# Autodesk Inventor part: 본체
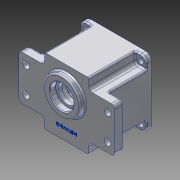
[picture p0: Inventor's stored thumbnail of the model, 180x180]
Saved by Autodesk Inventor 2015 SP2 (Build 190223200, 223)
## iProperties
Created: 2015-06
Part Number: 본체
Material: 알루미늄 6061
Document SubType Name: Modeling
Designer: AMC
Density: 2.7 g/cm^3
Appearance: 알루미늄 - 평지
Mass: 703.486 g
Surface Area: 672.192 cm^2
Volume: 260.55 cm^3
Author: AMC
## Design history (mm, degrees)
sketch "스케치1"
  geometry: L1 (-45, 45)-(45, 45); L2 (45, 45)-(45, -45); L3 (45, -45)-(-45, -45); L4 (-45, -45)-(-45, 45); 3 further points
  constraints: 8 end point, 2 midpoint, 2 parallel, 1 horizontal, 1 horizontal alignment, 1 perpendicular, 1 vertical alignment
  dimensions: "d0" = 90 distance of L1.start L1.end; "d1" = 90 distance of L3.end L1.start
extrude "돌출1" new body sketch "스케치1" distance "d2" = 70; taper "d3" = 0 deg
sketch "스케치2"
  geometry: L1 (45, 45)-(-45, 45) reference; L2 (-45, 45)-(-45, -45) reference; L3 (-45, -45)-(45, -45) reference; L4 (45, -45)-(45, 45) reference; L5 (-30, -65)-(30, -65); L6 (30, -65)-(30, 65); L7 (30, 65)-(-30, 65); L8 (-30, 65)-(-30, -65); 3 further points
  constraints: 8 end point, 2 midpoint, 2 parallel, 1 horizontal, 1 horizontal alignment, 1 perpendicular, 1 vertical alignment
  dimensions: "d4" = 130 distance of L5.end L6.end; "d5" = 60 distance of L6.end L7.end
extrude "돌출2" join sketch "스케치2" distance "d6" = 12; taper "d7" = 0 deg
sketch "스케치3"
  geometry: L1 (30, -45)-(45, -45) reference; L2 (45, -45)-(45, 45) reference; L3 (45, 45)-(30, 45) reference; L4 (30, 45)-(30, 65) reference; L5 (30, 65)-(-30, 65) reference; L6 (-30, 65)-(-30, 45) reference; L7 (-30, 45)-(-45, 45) reference; L8 (-45, 45)-(-45, -45) reference; L9 (-45, -45)-(-30, -45) reference; L10 (-30, -45)-(-30, -65) reference; L11 (-30, -65)-(30, -65) reference; L12 (30, -65)-(30, -45) reference; L13 (-45, -45)-(-30, -45); L14 (-30, -45)-(-30, -30); L15 (-30, -30)-(-45, -30); L16 (-45, -30)-(-45, -45); L17 (45, -45)-(30, -45); L18 (30, -45)-(30, -30); L19 (30, -30)-(45, -30); L20 (45, -30)-(45, -45); L21 (45, 45)-(30, 45); L22 (30, 45)-(30, 30); L23 (30, 30)-(45, 30); L24 (45, 30)-(45, 45); L25 (-45, 45)-(-30, 45); L26 (-30, 45)-(-30, 30); L27 (-30, 30)-(-45, 30); L28 (-45, 30)-(-45, 45); 1 further point
  constraints: 32 end point, 8 parallel, 4 horizontal, 4 perpendicular, 2 horizontal alignment, 2 vertical alignment
  dimensions: "d8" = 60 distance between parallel lines of L27 L15; "d9" = 15 distance of L13.end L14.end; "d10" = 60 distance between parallel lines of L22 L26; "d11" = 15 distance of L22.end L23.end
extrude "돌출3" cut sketch "스케치3" distance "d12" = 63; taper "d13" = 0 deg
sketch "스케치4"
  geometry: L1 (30, -45)-(-30, -45) reference; L2 (-30, 65)-(-30, 30) reference; L3 (-30, 30)-(-45, 30) reference; L4 (-45, 30)-(-45, -30) reference; L5 (-45, -30)-(-30, -30) reference; L6 (-30, -30)-(-30, -65) reference; L7 (-30, -65)-(30, -65) reference; L8 (30, -65)-(30, -30) reference; L9 (30, -30)-(45, -30) reference; L10 (45, -30)-(45, 30) reference; L11 (45, 30)-(30, 30) reference; L12 (30, 30)-(30, 65) reference; L13 (30, 65)-(-30, 65) reference; C1 r 25 at (11, 0); 1 further point
  constraints: 1 centre point, 1 horizontal alignment
  dimensions: "d14" = 50 diameter of C1; "d15" = 11 distance of point (0, 0) C1.centre
extrude "돌출4" join sketch "스케치4" distance "d16" = 7; taper "d17" = 0 deg
sketch "스케치5"
  geometry: 3 further points
  constraints: 2 coincident
hole "구멍1" sketch "스케치5" at (0, 0) diameter "d18" = 78; stored, may be unused: countersink angle "d22" = 90 deg, drill point angle "d24" = 0 deg; dims "d19" = 6, "d20" = 80, "d21" = 9, "d23" = 61
sketch "스케치6"
  geometry: C1 r 39 at (0, 0) reference; C2 r 25 at (-11, 0) reference; C3 r 20.5 at (-11, 0); 1 further point
  constraints: 1 centre point, 1 coincident
  dimensions: "d25" = 41 diameter of C3
extrude "돌출5" join sketch "스케치6" distance "d26" = 7; taper "d27" = 0 deg
hole "구멍2" diameter "d30" = 25; stored, may be unused: countersink angle "d34" = 90 deg, drill point angle "d36" = 0 deg; dims "d28" = 10, "d29" = 10, "d31" = 6, "d32" = 35, "d33" = 10, "d35" = 15
hole "구멍3" diameter "d39" = 32; stored, may be unused: countersink angle "d43" = 90 deg, drill point angle "d45" = 0 deg; dims "d37" = 10, "d38" = 10, "d40" = 6, "d41" = 35, "d42" = 10, "d44" = 8
sketch "스케치7"
  geometry: C1 r 39 at (0, 0) reference; A1 r 20.5 centre (-11, 0) between (8.117, 7.402) and (8.117, -7.402) reference; A2 r 14 centre (20, 0) between (8.117, -7.402) and (8.117, 7.402); 1 further point
  constraints: 4 point on circle, 1 centre point, 1 horizontal alignment
  dimensions: "d46" = 20 distance of A2.centre point (0, 0); "d47" = 28 diameter of A2
extrude "돌출6" join sketch "스케치7" distance "d48" = 7; taper "d49" = 0 deg
hole "구멍4" diameter "d52" = 19; stored, may be unused: countersink angle "d56" = 90 deg, drill point angle "d58" = 0 deg; dims "d50" = 10, "d51" = 10, "d53" = 6, "d54" = 22, "d55" = 7, "d57" = 8
sketch "스케치8"
  geometry: L1 (0, 0)-(-70.944, 0); L2 (0, 0)-(-50.344, 50.344); C1 r 39 at (0, 0) reference; A1 r 14 centre (20, 0) between (8.117, -7.402) and (8.117, 7.402) reference; A2 r 20.5 centre (-11, 0) between (8.117, 7.402) and (8.117, -7.402) reference; A3 r 35 centre (0, 0) between (-24.749, 24.749) and (-27.412, 21.762); A4 r 4 centre (-24.749, 24.749) between (-27.462, 21.809) and (-21.809, 27.462); A5 r 3.5 centre (-19.238, 29.836) between (-21.134, 32.777) and (-21.762, 27.412); A6 r 39 centre (0, 0) between (-32.777, 21.134) and (-21.134, 32.777) reference; A7 r 3.5 centre (-29.836, 19.238) between (-27.412, 21.762) and (-32.777, 21.134); 1 further point
  constraints: 13 point on circle, 4 centre point, 4 end point, 4 tangent, 1 coincident, 1 horizontal, 1 point on line
  dimensions: "d59" = 45 deg angle of L1 L2; "d60" = 70 diameter of A3; "d61" = 8 diameter of A4; "d62" = 7 diameter of A5; "d63" = 7 diameter of A7
extrude "돌출7" join sketch "스케치8" distance "d64" = 52; taper "d65" = 0 deg
hole "구멍5" diameter "d68" = 4; stored, may be unused: countersink angle "d72" = 90 deg, drill point angle "d74" = 118 deg; dims "d69" = 7.01, "d70" = 22, "d71" = 7, "d73" = 15, "d157" = 10, "d158" = 10
fillet "모깎기1" dims "d89" = 0.3
fillet "모깎기2" dims "d90" = 2
fillet "모깎기3" dims "d91" = 2
fillet "모깎기4" dims "d92" = 3
fillet "모깎기5" dims "d93" = 2
fillet "모깎기6" dims "d94" = 8
fillet "모깎기7" dims "d95" = 5
fillet "모깎기8" dims "d96" = 5
fillet "모깎기9" dims "d97" = 2
fillet "모깎기10" dims "d98" = 2
sketch "스케치10"
  geometry: L1 (43, 30)-(35, 30) reference; L2 (30, 35)-(30, 60) reference; L3 (25, 65)-(-25, 65) reference; L4 (-30, 60)-(-30, 35) reference; L5 (-35, 30)-(-43, 30) reference; L6 (-45, 28)-(-45, -28) reference; L7 (-43, -30)-(-35, -30) reference; L8 (-30, -35)-(-30, -60) reference; L9 (-25, -65)-(25, -65) reference; L10 (30, -60)-(30, -35) reference; L11 (35, -30)-(43, -30) reference; L12 (45, -28)-(45, 28) reference; C1 r 25 at (11, 0) reference; A1 r 37 centre (0, 0) between (-20.05, -31.096) and (20.05, -31.096) reference; A2 r 2 centre (43, 28) between (45, 28) and (43, 30) reference; A3 r 5 centre (35, 35) between (30, 35) and (35, 30) reference; A4 r 5 centre (25, 60) between (30, 60) and (25, 65) reference; A5 r 5 centre (-25, 60) between (-25, 65) and (-30, 60) reference; A6 r 5 centre (-35, 35) between (-35, 30) and (-30, 35) reference; A7 r 2 centre (-43, 28) between (-43, 30) and (-45, 28) reference; A8 r 2 centre (-43, -28) between (-45, -28) and (-43, -30) reference; A9 r 5 centre (-35, -35) between (-30, -35) and (-35, -30) reference; A10 r 5 centre (-25, -60) between (-30, -60) and (-25, -65) reference; A11 r 5 centre (25, -60) between (25, -65) and (30, -60) reference; A12 r 5 centre (35, -35) between (35, -30) and (30, -35) reference; A13 r 2 centre (43, -28) between (43, -30) and (45, -28) reference; 5 further points
  constraints: 2 horizontal alignment, 2 vertical alignment
  dimensions: "d99" = 35 distance of point (-17.5, -55) point (17.5, -55); "d100" = 12.5 distance from line of point (17.5, -55) L10; "d101" = 110 distance of point (17.5, -55) point (17.5, 55); "d102" = 10 distance from line of point (17.5, -55) L9
hole "구멍7" sketch "스케치10" at (17.5, -55), (-17.5, -55), (17.5, 55), (-17.5, 55) diameter "d103" = 9; stored, may be unused: countersink angle "d107" = 90 deg, drill point angle "d109" = 0 deg; dims "d104" = 12, "d105" = 22, "d106" = 7, "d108" = 15
hole "구멍8" diameter "d112" = 7; stored, may be unused: countersink angle "d116" = 90 deg, drill point angle "d118" = 0 deg; dims "d110" = 10, "d111" = 10, "d113" = 12, "d114" = 22, "d115" = 7, "d117" = 15
hole "구멍9" diameter "d121" = 7; stored, may be unused: countersink angle "d125" = 90 deg, drill point angle "d127" = 0 deg; dims "d119" = 10, "d120" = 10, "d122" = 12, "d123" = 22, "d124" = 7, "d126" = 15
hole "구멍10" diameter "d130" = 7; stored, may be unused: countersink angle "d134" = 90 deg, drill point angle "d136" = 0 deg; dims "d128" = 10, "d129" = 10, "d131" = 12, "d132" = 22, "d133" = 7, "d135" = 15
fillet "모깎기11" dims "d137" = 2
fillet "모깎기12" dims "d138" = 2
fillet "모깎기13" dims "d139" = 2
chamfer "모따기1" distance "d140" = 1; stored, may be unused: second distance "d141" = 2, angle "d142" = 45 deg
sketch "스케치11"
  geometry: L1 (-27.899, 14.518)-(-27.899, -14.518); L2 (-27.899, -14.518)-(-32.101, -14.518); L3 (-32.101, -14.518)-(-32.101, 14.518); L4 (-32.101, 14.518)-(-27.899, 14.518); L5 (-30, 14.518)-(-30, -14.518); L6 (-45, 28)-(-45, -28) reference; 2 further points
  constraints: 2 end point, 2 midpoint, 1 horizontal alignment, 2 other
  dimensions: "d143" = 15 distance between parallel lines of L5 L6
feature "엠보싱1" sketch "스케치11" dims "d6" = 12, "d7" = 0, "d144" = 0.5, "d145" = 0
fillet "모깎기14" dims "d146" = 2
fillet "모깎기15" dims "d147" = 2
hole "구멍11" diameter "d150" = 7; stored, may be unused: countersink angle "d154" = 90 deg, drill point angle "d156" = 118 deg; dims "d148" = 10, "d149" = 10, "d151" = 6, "d152" = 4, "d153" = 2, "d155" = 8
feature "스레드1" dims "d159" = 12, "d160" = 3
feature "스레드2" dims "d161" = 12, "d162" = 0
feature "스레드3" dims "d163" = 12, "d164" = 0
feature "스레드4" dims "d165" = 12, "d166" = 0
node "솔리드1"
pattern_circular "원형 패턴1" dims angle "d76" = 360 deg
node "투영된 루프1"
node "투영된 루프2"
node "투영된 루프3"
node "투영된 루프4"
node "투영된 루프5"
node "투영된 루프6"
node "투영된 루프8"
